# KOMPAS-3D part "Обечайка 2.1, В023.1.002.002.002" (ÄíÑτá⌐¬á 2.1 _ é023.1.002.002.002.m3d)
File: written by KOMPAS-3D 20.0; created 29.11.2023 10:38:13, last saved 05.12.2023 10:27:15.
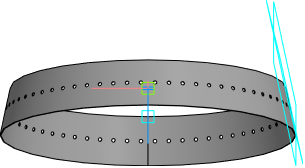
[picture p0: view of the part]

Document properties: Полное имя файла: C:\Обечайка 2.1 _ В023.1.002.002.002.m3d

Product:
- Part/product: Обечайка 2.1  | designation В023.1.002.002.002
    Масса: 17.6287
    source file: Обечайка 2.1 _ В023.1.002.002.002.cdw

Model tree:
1. Эскиз:1
2. Обечайка:1
     Расстояние 1 = 200; Угол 1 = 11.9; Толщина листового тела = 3; Коэффициент = 0.48; Величина сгиба = 3.29028e-05; Уменьшение сгиба = 2.125
3. Сгиб(1) - Обечайка:1
     Радиус сгиба = 569.7; Коэффициент = 0.48; Величина сгиба = 10; Зазор = 0.1
4. Касательная плоскость:1  (with: Обечайка:1)
5. Эскиз:3  (with: Обечайка:1)
6. Массив по концентрической сетке:1  (2 pattern instances)
7. Эскиз:5
8. Вырез в листовом теле:1  (with: Обечайка:1)
     Глубина выреза = 1266.75
9. Массив по концентрической сетке:5  (with: Вырез в листовом теле:1, Эскиз:5)  (64 pattern instances)
     Шаг 2 = 360
10. Плоскость, касательная в точке:1  (with: Обечайка:1)
11. Развертка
